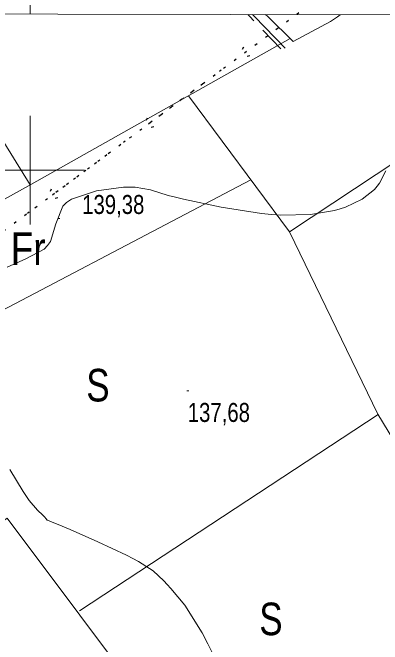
# Model space of a CAD drawing. Extents: x 483855 to 488461, y 4388206 to 4391419.
# Drawn here: x 484491.9 to 484662.2, y 4390781.6 to 4391072.6 of the extents above; entities that cross this region are included whole.
import ezdxf
from ezdxf.enums import TextEntityAlignment as Align

# ---------------------------------------------------------------- set-up
doc = ezdxf.new("R2010")
doc.units = 0
doc.header["$LTSCALE"] = 4
doc.linetypes.add('DOTTED', pattern=[1.5, 0.3, -1.2])
doc.linetypes.add('MEDIUM_DASHED', pattern=[4.5, 3, -1.5])
for name, color, linetype, lineweight in [('1', 7, 'Continuous', 13), ('38', 7, 'Continuous', 25), ('43', 7, 'DOTTED', 25), ('51', 7, 'Continuous', 13), ('7', 7, 'Continuous', 13), ('9', 7, 'Continuous', 13)]:
    doc.layers.add(name, color=color, linetype=linetype, lineweight=lineweight)
doc.layers.add('31', color=7, linetype='Continuous')

msp = doc.modelspace()

# ---------------------------------------------------------------- linework, layer by layer
at = {"layer": '1'}
for p, q in [((484500, 4391071.86), (484500, 4391143.22)), ((484500, 4391025), (484500, 4390975)), ((484475, 4391000), (484525, 4391000))]:
    msp.add_line(p, q, dxfattribs=at)
msp.add_lwpolyline([(484115.5, 4391072.6), (487689.7, 4391065.7), (487685.8, 4388753.5), (484110.5, 4388760.3)], close=True, dxfattribs=at)
at = {"layer": '38', "linetype": 'MEDIUM_DASHED'}
for p, q in [((484601.09, 4391070.73), (484600.18, 4391071.66)), ((484601.09, 4391070.73), (484600.18, 4391071.66)), ((484615.51, 4391055.86), (484601.09, 4391070.73))]:
    msp.add_line(p, q, dxfattribs=at)
at = {"layer": '38'}
for p, q in [((484603.32, 4391070.72), (484602.41, 4391071.66)), ((484603.32, 4391070.72), (484602.41, 4391071.66)), ((484617.43, 4391056.17), (484603.32, 4391070.72))]:
    msp.add_line(p, q, dxfattribs=at)
at = {"layer": '43'}
for p, q in [((484623.79, 4391072.48), (484406.1, 4390911.48)), ((484623.79, 4391072.48), (484595.65, 4391051.67)), ((484598.18, 4391056.65), (484595.65, 4391051.67)), ((484601.16, 4391052.63), (484595.65, 4391051.67)), ((484588.01, 4391046.02), (484587.21, 4391045.42)), ((484579.57, 4391039.78), (484551.43, 4391018.96)), ((484553.96, 4391023.95), (484551.43, 4391018.96)), ((484556.94, 4391019.93), (484551.43, 4391018.96)), ((484543.79, 4391013.31), (484542.99, 4391012.72)), ((484535.35, 4391007.07), (484507.21, 4390986.26)), ((484509.74, 4390991.24), (484507.21, 4390986.26)), ((484512.72, 4390987.22), (484507.21, 4390986.26)), ((484499.57, 4390980.61), (484498.77, 4390980.02))]:
    msp.add_line(p, q, dxfattribs=at)
at = {"layer": '51'}
for p, q in [((484608.42, 4391071.65), (484609.38, 4391070.71)), ((484641.46, 4391070.65), (484642.83, 4391071.58)), ((484660.23, 4390887.54), (484522.79, 4390796.99))]:
    msp.add_line(p, q, dxfattribs=at)
for points in [[(484609.38, 4391070.71), (484621.08, 4391059.33), (484638.32, 4391068.51), (484641.46, 4391070.65)], [(484619.76, 4391060.63), (484500.57, 4390993.64), (484432.52, 4390955.8), (484389.64, 4391028.72)], [(484837.6, 4390995.62), (484784.84, 4390963.95), (484728.68, 4391043.9), (484619.42, 4390971.63)], [(484572.93, 4391034.32), (484619.42, 4390971.63), (484660.14, 4390887.68), (484721.67, 4390786.29)], [(484410.47, 4390997.02), (484475.45, 4391028.26), (484480.11, 4391025.41), (484499.98, 4390993.31)], [(484601.7, 4390995.54), (484453.73, 4390917.88), (484419.26, 4390899.22), (484336.23, 4390845.75)], [(484484.36, 4390758.84), (484447.76, 4390805.87), (484447.83, 4390810.45), (484452.18, 4390814.35), (484489.49, 4390839.77), (484589.78, 4390705.66)]]:
    msp.add_lwpolyline(points, dxfattribs=at)
at = {"layer": '7'}
for p, q in [((484512.69, 4390977.69), (484513.69, 4390977.69)), ((484572.09, 4390898.42), (484573.09, 4390898.42))]:
    msp.add_line(p, q, dxfattribs=at)
at = {"layer": '9'}
for points in [[(484663.72, 4390999.78), (484660.88, 4390994.03), (484659.78, 4390992.57), (484658.54, 4390991.17), (484652.91, 4390986.62), (484645.29, 4390983.01), (484642.79, 4390982.21), (484640.13, 4390981.49), (484629.14, 4390979.61), (484615.46, 4390979.33), (484611.11, 4390979.62), (484606.52, 4390980.06), (484587.9, 4390983.01), (484570.61, 4390986.65), (484566.86, 4390987.53), (484563.56, 4390988.36), (484555.38, 4390990.93), (484548.38, 4390992.21), (484545.83, 4390992.24), (484543, 4390992.13)], [(484543, 4390992.13), (484530.56, 4390990.53), (484519.05, 4390986.66), (484516.81, 4390985.11), (484514.98, 4390983.36), (484511.81, 4390975.33), (484509.39, 4390967.16), (484508.04, 4390965.32), (484506.39, 4390963.67), (484497.95, 4390959.23), (484489.38, 4390955.28)], [(484490.7, 4390862.14), (484496.84, 4390851.96), (484498.28, 4390849.79), (484499.59, 4390847.9), (484503.38, 4390843.38), (484505.82, 4390841.14), (484506.3, 4390840.68), (484506.68, 4390840.28), (484507.34, 4390839.42), (484507.71, 4390838.99), (484507.91, 4390838.87), (484508.16, 4390838.74), (484509.42, 4390838.27), (484513.69, 4390836.53), (484515.83, 4390835.61), (484518.39, 4390834.49), (484531.1, 4390828.87), (484544.39, 4390822.62), (484547.32, 4390821.12), (484549.92, 4390819.71), (484556.59, 4390815.43), (484561.58, 4390810.8), (484563.13, 4390809.16), (484564.74, 4390807.37), (484571.17, 4390799.65), (484579.15, 4390786.87), (484581.75, 4390781.9), (484584.52, 4390776.31)]]:
    msp.add_lwpolyline(points, dxfattribs=at)

# ---------------------------------------------------------------- texts
at = {"layer": '31'}
for s, width, p in [('Fr', 0.85, (484499.09, 4390956.4)), ('S', 0.8, (484531.23, 4390893.49)), ('S', 0.8, (484610.89, 4390785.84))]:
    msp.add_text(s, height=15, dxfattribs=dict(at, width=width)).set_placement(p, align=Align.CENTER)
at = {"layer": '7', "width": 0.8}
for s, p in [('139,38', (484523.97, 4390979.84)), ('137,68', (484572.59, 4390884.05))]:
    msp.add_text(s, height=8.75, dxfattribs=at).set_placement(p)

doc.saveas('drawing.dxf')
